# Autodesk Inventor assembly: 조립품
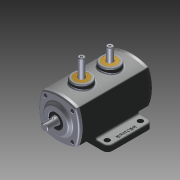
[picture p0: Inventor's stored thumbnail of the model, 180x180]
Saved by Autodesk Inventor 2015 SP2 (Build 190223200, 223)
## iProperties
Created: 2015-06
Part Number: 조립품
Document SubType Name: Assembly
Designer: AMC
Mass: 849.52 g
Surface Area: 1894.53 cm^2
Volume: 720.806 cm^3
Density: 1.17857 g/cm^3
Author: AMC
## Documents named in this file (12)
- C:\Users\AMC\Desktop\350620V1008\조립품.iam
- C:\Users\AMC\Desktop\350620V1008\M4-소켓머리.ipt
- C:\Users\AMC\Desktop\350620V1008\뒷커버.ipt
- C:\Users\AMC\Desktop\350620V1008\베어링 6203.ipt
- C:\Users\AMC\Desktop\350620V1008\본체.ipt
- C:\Users\AMC\Desktop\350620V1008\부시.ipt
- C:\Users\AMC\Desktop\350620V1008\스프링10.ipt
- C:\Users\AMC\Desktop\350620V1008\스프링11.ipt
- C:\Users\AMC\Desktop\350620V1008\슬라이더.ipt
- C:\Users\AMC\Desktop\350620V1008\앞커버.ipt
- C:\Users\AMC\Desktop\350620V1008\오일실.ipt
- C:\Users\AMC\Desktop\350620V1008\축.ipt
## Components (11 placed, 3 different names)
1. 7-베어링 6203:1
2. 8-오일실:1
3. 7-베어링 6203:2
4. 9-M4-소켓머리:1
5. 9-M4-소켓머리:3
6. 9-M4-소켓머리:4
7. 9-M4-소켓머리:5
8. 9-M4-소켓머리:2
9. 9-M4-소켓머리:6
10. 9-M4-소켓머리:7
11. 9-M4-소켓머리:8
